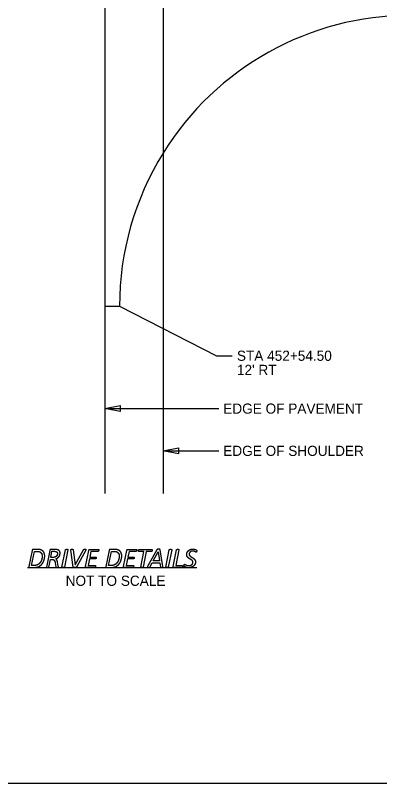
# Model space of a CAD drawing. Extents: x 0 to 3518, y -260 to 220.
# Drawn here: x 60.2 to 110.3, y 5 to 110.7 of the extents above; entities that cross this region are included whole.
import ezdxf

# ---------------------------------------------------------------- set-up
doc = ezdxf.new("R2010")
doc.units = 0
for name, color, linetype in [('DR_X_Culvert', 7, 'Continuous'), ('GE_P_Alignment_100_Stations', 7, 'Continuous'), ('MT_P_Temp_Road', 7, 'Continuous'), ('PF_P_Grade_Line', 7, 'Continuous'), ('PF_X_Ground_Line', 7, 'Continuous'), ('SC_Scratch2', 7, 'Continuous'), ('TX_P_1', 7, 'Continuous')]:
    doc.layers.add(name, color=color, linetype=linetype)

msp = doc.modelspace()

# ---------------------------------------------------------------- linework, layer by layer
at = {"layer": 'DR_X_Culvert'}
for p, q in [((62.52, 37.08), (62.08, 34.87)), ((63.21, 37.22), (62.68, 37.22)), ((64.94, 37.08), (64.48, 34.78)), ((65.65, 37.22), (65.11, 37.22)), ((66.62, 34.78), (67.1, 37.17)), ((67.43, 37.17), (66.95, 34.78)), ((68.18, 34.79), (67.83, 37.12)), ((69.9, 37.1), (68.62, 34.79)), ((69.86, 34.87), (70.31, 37.08)), ((70.46, 37.22), (71.64, 37.22)), ((71.68, 37.16), (71.68, 37.16)), ((73.12, 37.08), (72.68, 34.87)), ((73.81, 37.22), (73.28, 37.22)), ((75.1, 34.87), (75.54, 37.08)), ((75.69, 37.22), (76.87, 37.22)), ((76.92, 37.16), (76.92, 37.16)), ((77.26, 37.22), (78.99, 37.22)), ((79.7, 37.16), (78.4, 34.85)), ((79.04, 37.15), (79.04, 37.15)), ((80.51, 34.85), (80.14, 37.16)), ((80.91, 34.78), (81.39, 37.17)), ((81.72, 37.17), (81.24, 34.78)), ((81.92, 34.87), (82.38, 37.17)), ((85.17, 37.03), (85.17, 37.03)), ((63.9, 36.29), (63.9, 36.29)), ((64.25, 36.32), (64.25, 36.32)), ((66.01, 36.65), (66.01, 36.65)), ((66.36, 36.7), (66.36, 36.7)), ((74.5, 36.29), (74.5, 36.29)), ((74.85, 36.32), (74.85, 36.32)), ((65.68, 35.39), (65.78, 34.8)), ((66.12, 34.91), (66.02, 35.46)), ((83.22, 34.95), (83.22, 34.95)), ((61.9, 34.73), (85.17, 34.73)), ((62.18, 34.73), (62.73, 34.73)), ((71.15, 34.73), (69.96, 34.73)), ((72.78, 34.73), (73.33, 34.73)), ((76.39, 34.73), (75.19, 34.73)), ((83.12, 34.73), (82.02, 34.73))]:
    msp.add_line(p, q, dxfattribs=at)
for points in [[(68.17, 37.16), (68.46, 35.07), (68.46, 35.07), (69.57, 37.17)], [(82.71, 37.17), (82.29, 35.02), (83.18, 35.02)], [(62.78, 35.01), (62.43, 35.01), (62.82, 36.94), (63.17, 36.94)], [(65.37, 36.11), (65.08, 36.11), (65.25, 36.95), (65.59, 36.95)], [(71.58, 36.94), (70.61, 36.94), (70.45, 36.16), (71.29, 36.16)], [(73.38, 35.01), (73.03, 35.01), (73.42, 36.94), (73.77, 36.94)], [(76.82, 36.94), (75.85, 36.94), (75.69, 36.16), (76.53, 36.16)], [(77.47, 34.78), (77.9, 36.94), (77.2, 36.94)], [(78.93, 36.94), (78.23, 36.94), (77.8, 34.78)], [(64.81, 34.78), (65.03, 35.84), (65.25, 35.84)], [(71.24, 35.9), (70.4, 35.9), (70.22, 35.01), (71.21, 35.01)], [(76.47, 35.9), (75.63, 35.9), (75.46, 35.01), (76.45, 35.01)], [(78.73, 34.78), (79.05, 35.38), (80.09, 35.38), (80.18, 34.78)]]:
    msp.add_lwpolyline(points, dxfattribs=at)
msp.add_lwpolyline([(79.86, 36.89), (80.05, 35.65), (79.19, 35.65), (79.86, 36.89)], close=True, dxfattribs=at)
for points in [[(62.58, 37.19), (62.53, 37.16), (62.52, 37.08)], [(62.68, 37.22), (62.62, 37.22), (62.58, 37.19)], [(63.68, 37.16), (63.49, 37.22), (63.21, 37.22)], [(63.99, 36.98), (63.87, 37.1), (63.68, 37.16)], [(64.18, 36.7), (64.12, 36.87), (63.99, 36.98)], [(65.01, 37.19), (64.96, 37.16), (64.94, 37.08)], [(65.11, 37.22), (65.05, 37.22), (65.01, 37.19)], [(65.96, 37.18), (65.82, 37.22), (65.65, 37.22)], [(66.18, 37.08), (66.09, 37.15), (65.96, 37.18)], [(66.32, 36.92), (66.27, 37.02), (66.18, 37.08)], [(67.1, 37.17), (67.1, 37.18), (67.11, 37.2)], [(67.11, 37.2), (67.12, 37.21), (67.15, 37.21)], [(67.15, 37.21), (67.17, 37.22), (67.2, 37.23)], [(67.2, 37.23), (67.23, 37.23), (67.28, 37.23)], [(67.28, 37.23), (67.32, 37.23), (67.35, 37.23)], [(67.35, 37.23), (67.38, 37.22), (67.4, 37.21)], [(67.4, 37.21), (67.42, 37.21), (67.43, 37.2)], [(67.43, 37.2), (67.43, 37.18), (67.43, 37.17)], [(67.82, 37.18), (67.83, 37.2), (67.84, 37.21)], [(67.83, 37.12), (67.82, 37.15), (67.82, 37.18)], [(67.84, 37.21), (67.86, 37.22), (67.89, 37.23)], [(67.89, 37.23), (67.93, 37.23), (67.98, 37.23)], [(67.98, 37.23), (68.04, 37.23), (68.08, 37.23)], [(68.08, 37.23), (68.11, 37.23), (68.13, 37.22)], [(68.13, 37.22), (68.15, 37.21), (68.16, 37.2)], [(68.16, 37.2), (68.16, 37.18), (68.17, 37.16)], [(69.57, 37.17), (69.58, 37.18), (69.59, 37.2)], [(69.59, 37.2), (69.6, 37.21), (69.62, 37.22)], [(69.62, 37.22), (69.65, 37.23), (69.68, 37.23)], [(69.68, 37.23), (69.72, 37.23), (69.77, 37.23)], [(69.77, 37.23), (69.83, 37.23), (69.87, 37.23)], [(69.87, 37.23), (69.9, 37.22), (69.92, 37.21)], [(69.92, 37.17), (69.92, 37.14), (69.9, 37.1)], [(69.92, 37.21), (69.93, 37.19), (69.92, 37.17)], [(70.31, 37.08), (70.32, 37.16), (70.37, 37.19)], [(70.37, 37.19), (70.42, 37.22), (70.46, 37.22)], [(71.65, 36.99), (71.63, 36.97), (71.62, 36.96)], [(71.64, 37.22), (71.68, 37.22), (71.68, 37.16)], [(71.66, 37.04), (71.66, 37.01), (71.65, 36.99)], [(71.68, 37.08), (71.67, 37.06), (71.66, 37.04)], [(71.68, 37.16), (71.68, 37.15), (71.68, 37.13)], [(71.68, 37.13), (71.68, 37.11), (71.68, 37.08)], [(73.18, 37.19), (73.13, 37.16), (73.12, 37.08)], [(73.28, 37.22), (73.22, 37.22), (73.18, 37.19)], [(74.28, 37.16), (74.09, 37.22), (73.81, 37.22)], [(74.6, 36.98), (74.47, 37.1), (74.28, 37.16)], [(74.78, 36.7), (74.72, 36.87), (74.6, 36.98)], [(75.54, 37.08), (75.56, 37.16), (75.6, 37.19)], [(75.6, 37.19), (75.65, 37.22), (75.69, 37.22)], [(76.88, 36.99), (76.87, 36.97), (76.85, 36.96)], [(76.87, 37.22), (76.92, 37.22), (76.92, 37.16)], [(76.9, 37.04), (76.89, 37.01), (76.88, 36.99)], [(76.91, 37.08), (76.9, 37.06), (76.9, 37.04)], [(76.92, 37.13), (76.91, 37.11), (76.91, 37.08)], [(76.92, 37.16), (76.92, 37.15), (76.92, 37.13)], [(77.16, 37.04), (77.16, 37.06), (77.17, 37.08)], [(77.16, 37), (77.16, 37.02), (77.16, 37.04)], [(77.17, 36.96), (77.16, 36.97), (77.16, 37)], [(77.17, 37.08), (77.17, 37.11), (77.18, 37.13)], [(77.18, 37.13), (77.19, 37.15), (77.2, 37.17)], [(77.2, 37.17), (77.21, 37.19), (77.23, 37.21)], [(77.23, 37.21), (77.24, 37.22), (77.26, 37.22)], [(79, 36.98), (78.99, 36.96), (78.97, 36.95)], [(78.99, 37.22), (79.02, 37.22), (79.03, 37.2)], [(79.02, 37.03), (79.01, 37), (79, 36.98)], [(79.03, 37.08), (79.02, 37.05), (79.02, 37.03)], [(79.03, 37.2), (79.04, 37.18), (79.04, 37.15)], [(79.04, 37.15), (79.04, 37.14), (79.03, 37.12)], [(79.03, 37.12), (79.03, 37.1), (79.03, 37.08)], [(79.73, 37.2), (79.71, 37.18), (79.7, 37.16)], [(79.77, 37.22), (79.74, 37.21), (79.73, 37.2)], [(79.83, 37.23), (79.79, 37.23), (79.77, 37.22)], [(79.92, 37.23), (79.87, 37.23), (79.83, 37.23)], [(80.03, 37.23), (79.99, 37.23), (79.92, 37.23)], [(80.09, 37.22), (80.07, 37.23), (80.03, 37.23)], [(80.12, 37.2), (80.12, 37.21), (80.09, 37.22)], [(80.14, 37.16), (80.13, 37.18), (80.12, 37.2)], [(81.39, 37.17), (81.39, 37.18), (81.41, 37.2)], [(81.41, 37.2), (81.42, 37.21), (81.44, 37.21)], [(81.44, 37.21), (81.46, 37.22), (81.49, 37.23)], [(81.49, 37.23), (81.52, 37.23), (81.57, 37.23)], [(81.57, 37.23), (81.62, 37.23), (81.65, 37.23)], [(81.65, 37.23), (81.68, 37.22), (81.7, 37.21)], [(81.7, 37.21), (81.71, 37.21), (81.72, 37.2)], [(81.72, 37.2), (81.73, 37.18), (81.72, 37.17)], [(82.38, 37.17), (82.39, 37.18), (82.4, 37.2)], [(82.4, 37.2), (82.41, 37.21), (82.43, 37.21)], [(82.43, 37.21), (82.45, 37.22), (82.48, 37.23)], [(82.48, 37.23), (82.52, 37.23), (82.56, 37.23)], [(82.56, 37.23), (82.61, 37.23), (82.64, 37.23)], [(82.64, 37.23), (82.67, 37.22), (82.69, 37.21)], [(82.69, 37.21), (82.71, 37.21), (82.71, 37.2)], [(82.71, 37.2), (82.72, 37.18), (82.71, 37.17)], [(83.85, 36.81), (83.91, 36.94), (84.02, 37.04)], [(84.02, 37.04), (84.13, 37.14), (84.28, 37.2)], [(84.28, 37.2), (84.44, 37.26), (84.63, 37.26)], [(84.63, 37.26), (84.72, 37.26), (84.81, 37.24)], [(84.81, 37.24), (84.89, 37.23), (84.96, 37.2)], [(84.96, 37.2), (85.02, 37.18), (85.07, 37.16)], [(85.07, 37.16), (85.12, 37.13), (85.14, 37.11)], [(85.14, 37.11), (85.15, 37.1), (85.16, 37.08)], [(85.16, 37.08), (85.17, 37.06), (85.17, 37.03)], [(85.17, 37), (85.17, 36.98), (85.16, 36.96)], [(85.17, 37.03), (85.17, 37.02), (85.17, 37)], [(63.17, 36.94), (63.38, 36.94), (63.52, 36.9)], [(63.52, 36.9), (63.65, 36.85), (63.73, 36.76)], [(63.73, 36.76), (63.82, 36.68), (63.86, 36.56)], [(63.87, 36.01), (63.85, 35.86), (63.79, 35.72)], [(63.86, 36.56), (63.9, 36.44), (63.9, 36.29)], [(63.9, 36.29), (63.9, 36.16), (63.87, 36.01)], [(64.17, 35.79), (64.21, 35.93), (64.23, 36.06)], [(64.25, 36.32), (64.25, 36.53), (64.18, 36.7)], [(64.23, 36.06), (64.25, 36.2), (64.25, 36.32)], [(65.66, 36.16), (65.54, 36.11), (65.37, 36.11)], [(65.59, 36.95), (65.7, 36.95), (65.78, 36.93)], [(65.86, 36.28), (65.78, 36.2), (65.66, 36.16)], [(65.76, 35.92), (65.91, 35.97), (66.02, 36.05)], [(65.78, 36.93), (65.86, 36.9), (65.91, 36.86)], [(65.97, 36.45), (65.93, 36.35), (65.86, 36.28)], [(65.91, 36.86), (65.96, 36.82), (65.98, 36.77)], [(66.01, 36.65), (66.01, 36.55), (65.97, 36.45)], [(65.98, 36.77), (66.01, 36.71), (66.01, 36.65)], [(66.02, 36.05), (66.14, 36.13), (66.21, 36.23)], [(66.21, 36.23), (66.29, 36.33), (66.33, 36.45)], [(66.36, 36.7), (66.36, 36.82), (66.32, 36.92)], [(66.33, 36.45), (66.36, 36.57), (66.36, 36.7)], [(71.3, 35.94), (71.29, 35.92), (71.27, 35.91)], [(71.29, 36.16), (71.31, 36.16), (71.33, 36.15)], [(71.32, 35.98), (71.31, 35.96), (71.3, 35.94)], [(71.33, 36.03), (71.32, 36), (71.32, 35.98)], [(71.33, 36.15), (71.34, 36.13), (71.34, 36.1)], [(71.34, 36.1), (71.34, 36.09), (71.33, 36.07)], [(71.33, 36.07), (71.33, 36.05), (71.33, 36.03)], [(71.62, 36.96), (71.6, 36.94), (71.58, 36.94)], [(73.77, 36.94), (73.98, 36.94), (74.12, 36.9)], [(74.12, 36.9), (74.25, 36.85), (74.33, 36.76)], [(74.33, 36.76), (74.42, 36.68), (74.46, 36.56)], [(74.47, 36.01), (74.45, 35.86), (74.39, 35.72)], [(74.46, 36.56), (74.5, 36.44), (74.5, 36.29)], [(74.5, 36.29), (74.5, 36.16), (74.47, 36.01)], [(74.77, 35.79), (74.81, 35.93), (74.83, 36.06)], [(74.85, 36.32), (74.85, 36.53), (74.78, 36.7)], [(74.83, 36.06), (74.85, 36.2), (74.85, 36.32)], [(76.53, 35.94), (76.52, 35.92), (76.51, 35.91)], [(76.53, 36.16), (76.55, 36.16), (76.56, 36.15)], [(76.55, 35.98), (76.54, 35.96), (76.53, 35.94)], [(76.56, 36.03), (76.56, 36), (76.55, 35.98)], [(76.56, 36.15), (76.57, 36.13), (76.57, 36.1)], [(76.57, 36.07), (76.57, 36.05), (76.56, 36.03)], [(76.57, 36.1), (76.57, 36.09), (76.57, 36.07)], [(76.85, 36.96), (76.84, 36.94), (76.82, 36.94)], [(77.2, 36.94), (77.18, 36.94), (77.17, 36.96)], [(78.97, 36.95), (78.95, 36.94), (78.93, 36.94)], [(83.79, 36.52), (83.79, 36.68), (83.85, 36.81)], [(83.82, 36.31), (83.79, 36.4), (83.79, 36.52)], [(83.92, 36.14), (83.86, 36.21), (83.82, 36.31)], [(84.06, 36.01), (83.98, 36.07), (83.92, 36.14)], [(84.21, 35.91), (84.13, 35.96), (84.06, 36.01)], [(84.16, 36.71), (84.13, 36.63), (84.13, 36.55)], [(84.13, 36.55), (84.13, 36.47), (84.17, 36.4)], [(84.25, 36.85), (84.19, 36.79), (84.16, 36.71)], [(84.17, 36.4), (84.21, 36.34), (84.27, 36.29)], [(84.4, 36.94), (84.31, 36.91), (84.25, 36.85)], [(84.27, 36.29), (84.33, 36.24), (84.4, 36.19)], [(84.6, 36.98), (84.49, 36.98), (84.4, 36.94)], [(84.4, 36.19), (84.48, 36.14), (84.56, 36.09)], [(84.56, 36.09), (84.64, 36.05), (84.72, 35.99)], [(84.79, 36.96), (84.71, 36.98), (84.6, 36.98)], [(84.72, 35.99), (84.8, 35.94), (84.86, 35.86)], [(84.93, 36.9), (84.87, 36.93), (84.79, 36.96)], [(85.03, 36.85), (84.99, 36.87), (84.93, 36.9)], [(85.09, 36.83), (85.06, 36.83), (85.03, 36.85)], [(85.11, 36.84), (85.1, 36.83), (85.09, 36.83)], [(85.13, 36.87), (85.12, 36.85), (85.11, 36.84)], [(85.15, 36.91), (85.14, 36.88), (85.13, 36.87)], [(85.16, 36.96), (85.16, 36.93), (85.15, 36.91)], [(63.17, 35.06), (63.01, 35.01), (62.78, 35.01)], [(63.16, 34.77), (63.33, 34.81), (63.48, 34.88)], [(63.45, 35.22), (63.33, 35.12), (63.17, 35.06)], [(63.65, 35.44), (63.57, 35.32), (63.45, 35.22)], [(63.48, 34.88), (63.62, 34.96), (63.73, 35.06)], [(63.79, 35.72), (63.74, 35.57), (63.65, 35.44)], [(63.73, 35.06), (63.85, 35.16), (63.93, 35.28)], [(63.93, 35.28), (64.02, 35.39), (64.08, 35.53)], [(64.08, 35.53), (64.14, 35.66), (64.17, 35.79)], [(65.25, 35.84), (65.36, 35.84), (65.44, 35.81)], [(65.44, 35.81), (65.51, 35.77), (65.56, 35.71)], [(65.56, 35.71), (65.61, 35.65), (65.64, 35.57)], [(65.64, 35.57), (65.67, 35.49), (65.68, 35.39)], [(65.92, 35.77), (65.86, 35.89), (65.76, 35.92)], [(66.02, 35.46), (65.98, 35.65), (65.92, 35.77)], [(66.13, 34.84), (66.13, 34.87), (66.12, 34.91)], [(71.21, 35.01), (71.23, 35.01), (71.24, 34.99)], [(71.27, 35.91), (71.26, 35.9), (71.24, 35.9)], [(71.24, 34.99), (71.25, 34.98), (71.25, 34.94)], [(71.25, 34.94), (71.25, 34.93), (71.25, 34.91)], [(71.25, 34.91), (71.25, 34.89), (71.25, 34.87)], [(73.77, 35.06), (73.61, 35.01), (73.38, 35.01)], [(73.76, 34.77), (73.93, 34.81), (74.08, 34.88)], [(74.05, 35.22), (73.93, 35.12), (73.77, 35.06)], [(74.25, 35.44), (74.17, 35.32), (74.05, 35.22)], [(74.08, 34.88), (74.22, 34.96), (74.33, 35.06)], [(74.39, 35.72), (74.34, 35.57), (74.25, 35.44)], [(74.33, 35.06), (74.45, 35.16), (74.53, 35.28)], [(74.53, 35.28), (74.62, 35.39), (74.68, 35.53)], [(74.68, 35.53), (74.74, 35.66), (74.77, 35.79)], [(76.45, 35.01), (76.46, 35.01), (76.48, 34.99)], [(76.51, 35.91), (76.49, 35.9), (76.47, 35.9)], [(76.48, 34.99), (76.49, 34.98), (76.49, 34.94)], [(76.49, 34.91), (76.49, 34.89), (76.48, 34.87)], [(76.49, 34.94), (76.49, 34.93), (76.49, 34.91)], [(83.18, 35.02), (83.2, 35.02), (83.21, 35)], [(83.21, 34.88), (83.21, 34.85), (83.2, 34.83)], [(83.21, 35), (83.22, 34.98), (83.22, 34.95)], [(83.22, 34.92), (83.22, 34.9), (83.21, 34.88)], [(83.22, 34.95), (83.22, 34.94), (83.22, 34.92)], [(83.41, 34.99), (83.41, 35.01), (83.42, 35.03)], [(83.41, 34.96), (83.41, 34.97), (83.41, 34.99)], [(83.43, 34.88), (83.41, 34.91), (83.41, 34.96)], [(83.42, 35.03), (83.42, 35.06), (83.43, 35.08)], [(83.43, 35.08), (83.44, 35.11), (83.45, 35.13)], [(83.51, 34.83), (83.46, 34.86), (83.43, 34.88)], [(83.45, 35.13), (83.46, 35.15), (83.47, 35.16)], [(83.47, 35.16), (83.48, 35.17), (83.5, 35.17)], [(83.5, 35.17), (83.53, 35.17), (83.58, 35.14)], [(83.58, 35.14), (83.62, 35.11), (83.69, 35.08)], [(83.69, 35.08), (83.76, 35.04), (83.86, 35.01)], [(83.86, 35.01), (83.95, 34.98), (84.08, 34.98)], [(84.08, 34.98), (84.21, 34.98), (84.32, 35.02)], [(84.37, 35.82), (84.29, 35.86), (84.21, 35.91)], [(84.32, 35.02), (84.42, 35.05), (84.49, 35.12)], [(84.51, 35.72), (84.45, 35.77), (84.37, 35.82)], [(84.74, 34.93), (84.61, 34.82), (84.44, 34.76)], [(84.49, 35.12), (84.57, 35.18), (84.6, 35.27)], [(84.61, 35.6), (84.57, 35.67), (84.51, 35.72)], [(84.6, 35.27), (84.64, 35.36), (84.64, 35.45)], [(84.64, 35.45), (84.64, 35.54), (84.61, 35.6)], [(84.93, 35.18), (84.86, 35.03), (84.74, 34.93)], [(84.86, 35.86), (84.92, 35.79), (84.96, 35.7)], [(85, 35.48), (85, 35.32), (84.93, 35.18)], [(84.96, 35.7), (85, 35.61), (85, 35.48)], [(62.08, 34.87), (62.07, 34.83), (62.07, 34.8)], [(62.07, 34.8), (62.08, 34.78), (62.09, 34.76)], [(62.09, 34.76), (62.11, 34.74), (62.13, 34.74)], [(62.13, 34.74), (62.15, 34.73), (62.18, 34.73)], [(62.73, 34.73), (62.98, 34.73), (63.16, 34.77)], [(64.48, 34.78), (64.48, 34.76), (64.49, 34.75)], [(64.49, 34.75), (64.49, 34.74), (64.51, 34.73)], [(64.51, 34.73), (64.53, 34.73), (64.56, 34.72)], [(64.56, 34.72), (64.59, 34.72), (64.63, 34.72)], [(64.63, 34.72), (64.68, 34.72), (64.71, 34.72)], [(64.71, 34.72), (64.75, 34.73), (64.77, 34.74)], [(64.77, 34.74), (64.79, 34.74), (64.8, 34.75)], [(64.8, 34.75), (64.81, 34.77), (64.81, 34.78)], [(65.78, 34.8), (65.79, 34.78), (65.79, 34.76)], [(65.79, 34.76), (65.8, 34.75), (65.82, 34.74)], [(65.82, 34.74), (65.83, 34.73), (65.86, 34.72)], [(65.86, 34.72), (65.9, 34.72), (65.95, 34.72)], [(65.95, 34.72), (66, 34.72), (66.04, 34.72)], [(66.04, 34.72), (66.07, 34.73), (66.09, 34.73)], [(66.09, 34.73), (66.12, 34.74), (66.13, 34.75)], [(66.13, 34.78), (66.13, 34.81), (66.13, 34.84)], [(66.13, 34.75), (66.13, 34.77), (66.13, 34.78)], [(66.62, 34.75), (66.62, 34.77), (66.62, 34.78)], [(66.65, 34.74), (66.63, 34.74), (66.62, 34.75)], [(66.69, 34.72), (66.66, 34.73), (66.65, 34.74)], [(66.77, 34.72), (66.72, 34.72), (66.69, 34.72)], [(66.85, 34.72), (66.82, 34.72), (66.77, 34.72)], [(66.91, 34.74), (66.89, 34.73), (66.85, 34.72)], [(66.94, 34.75), (66.93, 34.74), (66.91, 34.74)], [(66.95, 34.78), (66.95, 34.77), (66.94, 34.75)], [(68.19, 34.75), (68.18, 34.77), (68.18, 34.79)], [(68.23, 34.73), (68.2, 34.74), (68.19, 34.75)], [(68.29, 34.72), (68.25, 34.73), (68.23, 34.73)], [(68.39, 34.72), (68.33, 34.72), (68.29, 34.72)], [(68.49, 34.72), (68.45, 34.72), (68.39, 34.72)], [(68.55, 34.73), (68.53, 34.73), (68.49, 34.72)], [(68.59, 34.75), (68.58, 34.74), (68.55, 34.73)], [(68.62, 34.79), (68.61, 34.77), (68.59, 34.75)], [(69.86, 34.8), (69.86, 34.83), (69.86, 34.87)], [(69.88, 34.76), (69.87, 34.78), (69.86, 34.8)], [(69.92, 34.74), (69.9, 34.74), (69.88, 34.76)], [(69.96, 34.73), (69.94, 34.73), (69.92, 34.74)], [(71.19, 34.74), (71.17, 34.73), (71.15, 34.73)], [(71.22, 34.77), (71.21, 34.75), (71.19, 34.74)], [(71.23, 34.82), (71.23, 34.79), (71.22, 34.77)], [(71.25, 34.87), (71.24, 34.84), (71.23, 34.82)], [(72.68, 34.87), (72.67, 34.83), (72.67, 34.8)], [(72.67, 34.8), (72.68, 34.78), (72.69, 34.76)], [(72.69, 34.76), (72.71, 34.74), (72.73, 34.74)], [(72.73, 34.74), (72.75, 34.73), (72.78, 34.73)], [(73.33, 34.73), (73.58, 34.73), (73.76, 34.77)], [(75.1, 34.8), (75.09, 34.83), (75.1, 34.87)], [(75.12, 34.76), (75.1, 34.78), (75.1, 34.8)], [(75.15, 34.74), (75.13, 34.74), (75.12, 34.76)], [(75.19, 34.73), (75.17, 34.73), (75.15, 34.74)], [(76.42, 34.74), (76.41, 34.73), (76.39, 34.73)], [(76.45, 34.77), (76.44, 34.75), (76.42, 34.74)], [(76.47, 34.82), (76.46, 34.79), (76.45, 34.77)], [(76.48, 34.87), (76.48, 34.84), (76.47, 34.82)], [(77.47, 34.75), (77.46, 34.77), (77.47, 34.78)], [(77.49, 34.74), (77.48, 34.74), (77.47, 34.75)], [(77.54, 34.72), (77.51, 34.73), (77.49, 34.74)], [(77.62, 34.72), (77.57, 34.72), (77.54, 34.72)], [(77.7, 34.72), (77.67, 34.72), (77.62, 34.72)], [(77.75, 34.74), (77.73, 34.73), (77.7, 34.72)], [(77.78, 34.75), (77.77, 34.74), (77.75, 34.74)], [(77.8, 34.78), (77.8, 34.77), (77.78, 34.75)], [(78.38, 34.78), (78.37, 34.76), (78.38, 34.74)], [(78.4, 34.85), (78.38, 34.81), (78.38, 34.78)], [(78.38, 34.74), (78.4, 34.73), (78.43, 34.72)], [(78.43, 34.72), (78.47, 34.72), (78.52, 34.72)], [(78.52, 34.72), (78.57, 34.72), (78.61, 34.72)], [(78.61, 34.72), (78.65, 34.73), (78.67, 34.73)], [(78.67, 34.73), (78.69, 34.74), (78.7, 34.75)], [(78.7, 34.75), (78.72, 34.77), (78.73, 34.78)], [(80.18, 34.78), (80.18, 34.76), (80.19, 34.75)], [(80.19, 34.75), (80.2, 34.74), (80.21, 34.73)], [(80.21, 34.73), (80.23, 34.73), (80.26, 34.72)], [(80.26, 34.72), (80.29, 34.72), (80.33, 34.72)], [(80.33, 34.72), (80.4, 34.72), (80.44, 34.72)], [(80.44, 34.72), (80.48, 34.73), (80.49, 34.74)], [(80.49, 34.74), (80.51, 34.75), (80.51, 34.78)], [(80.51, 34.78), (80.52, 34.81), (80.51, 34.85)], [(80.92, 34.75), (80.91, 34.77), (80.91, 34.78)], [(80.94, 34.74), (80.92, 34.74), (80.92, 34.75)], [(80.99, 34.72), (80.96, 34.73), (80.94, 34.74)], [(81.07, 34.72), (81.02, 34.72), (80.99, 34.72)], [(81.15, 34.72), (81.11, 34.72), (81.07, 34.72)], [(81.2, 34.74), (81.18, 34.73), (81.15, 34.72)], [(81.23, 34.75), (81.22, 34.74), (81.2, 34.74)], [(81.24, 34.78), (81.24, 34.77), (81.23, 34.75)], [(81.92, 34.8), (81.91, 34.83), (81.92, 34.87)], [(81.94, 34.76), (81.93, 34.78), (81.92, 34.8)], [(81.98, 34.74), (81.96, 34.74), (81.94, 34.76)], [(82.02, 34.73), (82, 34.73), (81.98, 34.74)], [(83.16, 34.74), (83.14, 34.73), (83.12, 34.73)], [(83.18, 34.78), (83.17, 34.76), (83.16, 34.74)], [(83.2, 34.83), (83.2, 34.8), (83.18, 34.78)], [(83.65, 34.76), (83.57, 34.79), (83.51, 34.83)], [(83.83, 34.71), (83.73, 34.73), (83.65, 34.76)], [(84.05, 34.69), (83.93, 34.69), (83.83, 34.71)], [(84.44, 34.76), (84.26, 34.69), (84.05, 34.69)]]:
    msp.add_open_spline(points, degree=2, dxfattribs=at)
at = {"layer": 'GE_P_Alignment_100_Stations'}
msp.add_line((72.54, 201.81), (72.54, 44.91), dxfattribs=at)
at = {"layer": 'MT_P_Temp_Road'}
msp.add_line((72.54, 70.66), (74.54, 70.66), dxfattribs=at)
for start, end in [(90, 148.2117), (148.2117, 180)]:
    msp.add_arc((114.54, 70.66), 40, start, end, dxfattribs=at)
at = {"layer": 'PF_P_Grade_Line'}
msp.add_line((80.54, 201.81), (80.54, 44.91), dxfattribs=at)
at = {"layer": 'PF_X_Ground_Line'}
msp.add_lwpolyline([(15, 215), (335, 215), (335, 5), (15, 5)], close=True, dxfattribs=at)
at = {"layer": 'SC_Scratch2'}
for points in [[(74.64, 57), (74.64, 56.16), (72.54, 56.58)], [(82.64, 51.19), (82.64, 50.35), (80.54, 50.77)]]:
    msp.add_lwpolyline(points, close=True, dxfattribs=at)
at = {"layer": 'TX_P_1'}
for p, q in [((74.54, 70.66), (87.87, 63.85)), ((87.87, 63.85), (90.05, 63.85)), ((72.54, 56.58), (88.21, 56.58)), ((80.54, 50.77), (88.21, 50.77))]:
    msp.add_line(p, q, dxfattribs=at)

# ---------------------------------------------------------------- texts
for s, p in [('STA 452+54.50', (90.7, 63.15)), ("12' RT", (90.7, 61.2)), ('EDGE OF PAVEMENT', (88.82, 55.88)), ('EDGE OF SHOULDER', (88.82, 50.07)), ('NOT TO SCALE', (67.13, 32.2))]:
    msp.add_text(s, height=1.4, dxfattribs=at).set_placement(p)

doc.saveas('drawing.dxf')
